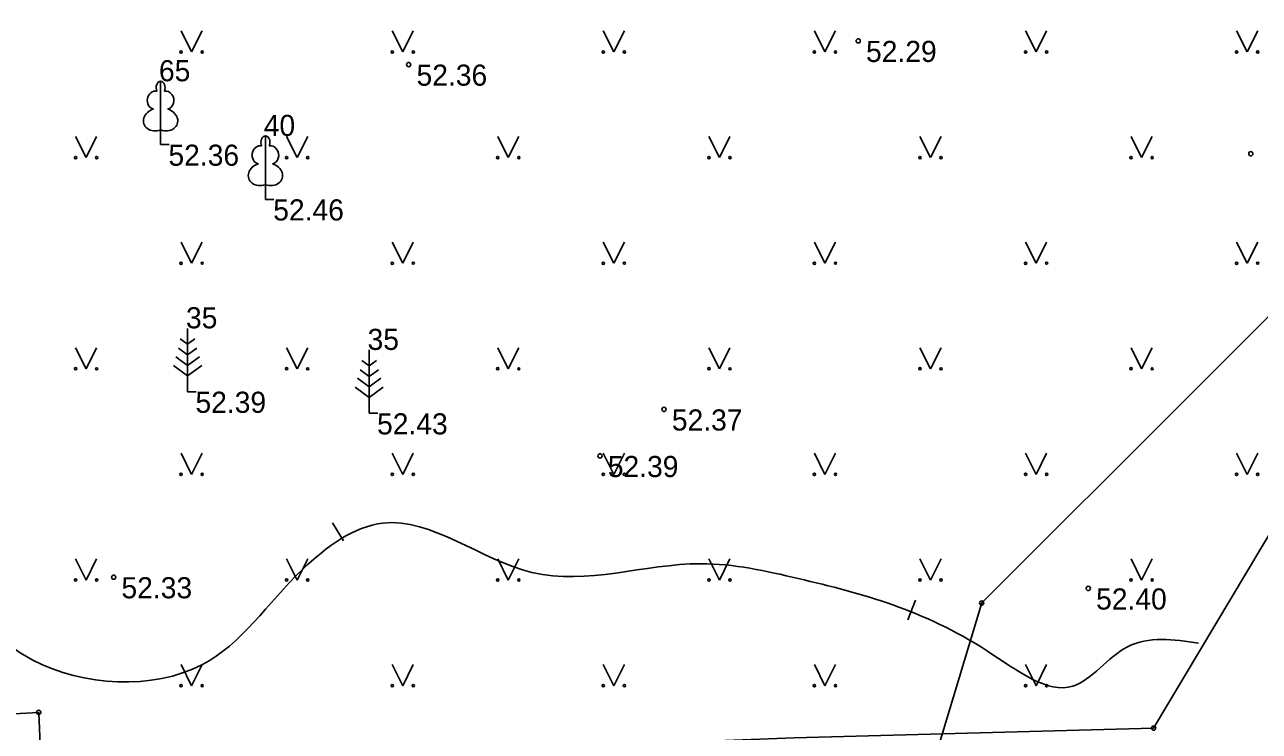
# Model space of a CAD drawing. Extents: x 619806 to 620082, y 405176 to 405386.
# Drawn here: x 619868.55 to 619897.79, y 405291.42 to 405308.14 of the extents above; entities that cross this region are included whole.
import ezdxf

# ---------------------------------------------------------------- set-up
doc = ezdxf.new("R2010")
doc.units = 0
for name, color, linetype in [('APGS_VADP_ZSPR_####_#', 7, 'Continuous'), ('CELI_CMAL_####_####_#', 7, 'Continuous'), ('RELJ_AATZ_####_TKST_#', 7, 'Continuous'), ('RELJ_ELEM_####_####_#', 7, 'Continuous'), ('RELJ_HORZ_PAMT_####_#', 7, 'Continuous'), ('TERT_DIAM_####_TKST_#', 7, 'Continuous'), ('TERT_ELEM_####_####_#', 7, 'Continuous')]:
    doc.layers.add(name, color=color, linetype=linetype)

msp = doc.modelspace()

# ---------------------------------------------------------------- linework, layer by layer
at = {"layer": 'APGS_VADP_ZSPR_####_#'}
msp.add_lwpolyline([(619926.053, 405342.093), (619924.906, 405341.871), (619913.437, 405323.942), (619914.167, 405323.421), (619913.311, 405323.727), (619901.199, 405304.503), (619901.88, 405304.137), (619901.118, 405304.337), (619891.212, 405294.458), (619889.151, 405287.633)], dxfattribs=at)
at = {"layer": 'CELI_CMAL_####_####_#'}
msp.add_lwpolyline([(619901.141, 405301.297), (619895.285, 405291.495), (619886.767, 405291.266), (619876.357, 405290.867), (619868.929, 405290.713), (619868.879, 405291.869), (619865.764, 405291.699), (619865.807, 405290.556), (619863.458, 405290.505), (619853.554, 405290.137), (619841.43, 405289.76), (619840.169, 405289.507), (619836.17, 405288.32), (619833.502, 405287.788), (619826.905, 405297.999), (619827.372, 405299.068), (619837.906, 405304.107), (619846.534, 405308.229), (619856.914, 405313.201), (619868.255, 405318.592), (619880.738, 405324.67), (619889.516, 405328.858), (619904.867, 405336.211)], dxfattribs=at)
at = {"layer": 'RELJ_ELEM_####_####_#'}
for centre in [(619888.287, 405307.762), (619877.641, 405307.201), (619897.586, 405305.09), (619883.688, 405299.039), (619882.171, 405297.938), (619870.652, 405295.068), (619893.736, 405294.802), (619891.212, 405294.458), (619868.879, 405291.869), (619895.285, 405291.495)]:
    msp.add_circle(centre, 0.05, dxfattribs=at)
at = {"layer": 'RELJ_HORZ_PAMT_####_#'}
for p, q in [((619875.834, 405296.356), (619876.098, 405295.931)), ((619889.647, 405294.525), (619889.465, 405294.06))]:
    msp.add_line(p, q, dxfattribs=at)
msp.add_spline([(619896.346, 405293.509), (619894.668, 405293.42), (619893.372, 405292.489), (619891.349, 405293.319), (619886.863, 405295.038), (619884.556, 405295.387), (619880.561, 405295.181), (619877.029, 405296.347), (619875.125, 405295.25), (619872.741, 405292.993), (619868.738, 405293.105), (619866.791, 405295.071), (619865.088, 405296.98), (619863.053, 405296.079), (619860.996, 405293.537), (619856.488, 405293.095), (619852.645, 405293.374), (619849.391, 405295.245), (619849.08, 405296.066), (619849.436, 405297.5), (619848.114, 405298.857), (619845.722, 405300.218), (619843.589, 405299.958), (619840.501, 405300.72), (619839.187, 405301.782), (619838.112, 405302.478), (619838.665, 405303.995), (619839.645, 405304.937)], degree=3, dxfattribs=at)
at = {"layer": 'TERT_ELEM_####_####_#'}
for p, q in [((619872.25, 405308), (619872.5, 405307.5)), ((619872.5, 405307.5), (619872.75, 405308)), ((619877.25, 405308), (619877.5, 405307.5)), ((619877.5, 405307.5), (619877.75, 405308)), ((619882.25, 405308), (619882.5, 405307.5)), ((619882.5, 405307.5), (619882.75, 405308)), ((619887.25, 405308), (619887.5, 405307.5)), ((619887.5, 405307.5), (619887.75, 405308)), ((619892.25, 405308), (619892.5, 405307.5)), ((619892.5, 405307.5), (619892.75, 405308)), ((619897.25, 405308), (619897.5, 405307.5)), ((619897.5, 405307.5), (619897.75, 405308)), ((619869.75, 405305.5), (619870, 405305)), ((619870, 405305), (619870.25, 405305.5)), ((619871.765, 405305.653), (619871.765, 405305.306)), ((619874.75, 405305.5), (619875, 405305)), ((619875, 405305), (619875.25, 405305.5)), ((619879.75, 405305.5), (619880, 405305)), ((619880, 405305), (619880.25, 405305.5)), ((619884.75, 405305.5), (619885, 405305)), ((619885, 405305), (619885.25, 405305.5)), ((619889.75, 405305.5), (619890, 405305)), ((619890, 405305), (619890.25, 405305.5)), ((619894.75, 405305.5), (619895, 405305)), ((619895, 405305), (619895.25, 405305.5)), ((619871.765, 405305.306), (619871.965, 405305.306)), ((619874.247, 405304.358), (619874.247, 405304.011)), ((619874.247, 405304.011), (619874.447, 405304.011)), ((619872.25, 405303), (619872.5, 405302.5)), ((619872.5, 405302.5), (619872.75, 405303)), ((619877.25, 405303), (619877.5, 405302.5)), ((619877.5, 405302.5), (619877.75, 405303)), ((619882.25, 405303), (619882.5, 405302.5)), ((619882.5, 405302.5), (619882.75, 405303)), ((619887.25, 405303), (619887.5, 405302.5)), ((619887.5, 405302.5), (619887.75, 405303)), ((619892.25, 405303), (619892.5, 405302.5)), ((619892.5, 405302.5), (619892.75, 405303)), ((619897.25, 405303), (619897.5, 405302.5)), ((619897.5, 405302.5), (619897.75, 405303)), ((619872.405, 405300.582), (619872.229, 405300.71)), ((619872.405, 405300.958), (619872.405, 405299.458)), ((619872.405, 405300.582), (619872.579, 405300.71)), ((619869.75, 405300.5), (619870, 405300)), ((619870, 405300), (619870.25, 405300.5)), ((619872.405, 405300.332), (619872.189, 405300.49)), ((619872.405, 405300.332), (619872.621, 405300.49)), ((619874.75, 405300.5), (619875, 405300)), ((619875, 405300), (619875.25, 405300.5)), ((619876.706, 405300.447), (619876.706, 405298.947)), ((619879.75, 405300.5), (619880, 405300)), ((619880, 405300), (619880.25, 405300.5)), ((619884.75, 405300.5), (619885, 405300)), ((619885, 405300), (619885.25, 405300.5)), ((619889.75, 405300.5), (619890, 405300)), ((619890, 405300), (619890.25, 405300.5)), ((619894.75, 405300.5), (619895, 405300)), ((619895, 405300), (619895.25, 405300.5)), ((619872.405, 405300.082), (619872.127, 405300.286)), ((619872.405, 405300.082), (619872.683, 405300.286)), ((619876.706, 405300.071), (619876.53, 405300.199)), ((619876.706, 405300.071), (619876.88, 405300.199)), ((619872.405, 405299.832), (619872.073, 405300.076)), ((619872.405, 405299.832), (619872.739, 405300.076)), ((619876.706, 405299.821), (619876.49, 405299.979)), ((619876.706, 405299.821), (619876.922, 405299.979)), ((619876.706, 405299.321), (619876.374, 405299.565)), ((619876.706, 405299.571), (619876.428, 405299.775)), ((619876.706, 405299.571), (619876.984, 405299.775)), ((619876.706, 405299.321), (619877.04, 405299.565)), ((619872.405, 405299.458), (619872.605, 405299.458)), ((619876.706, 405298.947), (619876.906, 405298.947)), ((619872.25, 405298), (619872.5, 405297.5)), ((619872.5, 405297.5), (619872.75, 405298)), ((619877.25, 405298), (619877.5, 405297.5)), ((619877.5, 405297.5), (619877.75, 405298)), ((619882.25, 405298), (619882.5, 405297.5)), ((619882.5, 405297.5), (619882.75, 405298)), ((619887.25, 405298), (619887.5, 405297.5)), ((619887.5, 405297.5), (619887.75, 405298)), ((619892.25, 405298), (619892.5, 405297.5)), ((619892.5, 405297.5), (619892.75, 405298)), ((619897.25, 405298), (619897.5, 405297.5)), ((619897.5, 405297.5), (619897.75, 405298)), ((619869.75, 405295.5), (619870, 405295)), ((619870, 405295), (619870.25, 405295.5)), ((619874.75, 405295.5), (619875, 405295)), ((619875, 405295), (619875.25, 405295.5)), ((619879.75, 405295.5), (619880, 405295)), ((619880, 405295), (619880.25, 405295.5)), ((619884.75, 405295.5), (619885, 405295)), ((619885, 405295), (619885.25, 405295.5)), ((619889.75, 405295.5), (619890, 405295)), ((619890, 405295), (619890.25, 405295.5)), ((619894.75, 405295.5), (619895, 405295)), ((619895, 405295), (619895.25, 405295.5)), ((619872.25, 405293), (619872.5, 405292.5)), ((619872.5, 405292.5), (619872.75, 405293)), ((619877.25, 405293), (619877.5, 405292.5)), ((619877.5, 405292.5), (619877.75, 405293)), ((619882.25, 405293), (619882.5, 405292.5)), ((619882.5, 405292.5), (619882.75, 405293)), ((619887.25, 405293), (619887.5, 405292.5)), ((619887.5, 405292.5), (619887.75, 405293)), ((619892.25, 405293), (619892.5, 405292.5)), ((619892.5, 405292.5), (619892.75, 405293))]:
    msp.add_line(p, q, dxfattribs=at)
for points in [[(619871.765, 405306.806), (619871.765, 405305.653)], [(619871.855, 405306.574), (619871.854, 405306.575)], [(619874.247, 405305.511), (619874.247, 405304.358)], [(619874.337, 405305.279), (619874.336, 405305.28)]]:
    msp.add_lwpolyline(points, dxfattribs=at)
for centre, radius in [((619872.25, 405307.5), 0.028), ((619872.75, 405307.5), 0.0263), ((619877.25, 405307.5), 0.028), ((619877.75, 405307.5), 0.0263), ((619882.25, 405307.5), 0.028), ((619882.75, 405307.5), 0.0263), ((619887.25, 405307.5), 0.028), ((619887.75, 405307.5), 0.0263), ((619892.25, 405307.5), 0.028), ((619892.75, 405307.5), 0.0263), ((619897.25, 405307.5), 0.028), ((619897.75, 405307.5), 0.0263), ((619869.75, 405305), 0.028), ((619870.25, 405305), 0.0263), ((619874.75, 405305), 0.028), ((619875.25, 405305), 0.0263), ((619879.75, 405305), 0.028), ((619880.25, 405305), 0.0263), ((619884.75, 405305), 0.028), ((619885.25, 405305), 0.0263), ((619889.75, 405305), 0.028), ((619890.25, 405305), 0.0263), ((619894.75, 405305), 0.028), ((619895.25, 405305), 0.0263), ((619872.25, 405302.5), 0.028), ((619872.75, 405302.5), 0.0263), ((619877.25, 405302.5), 0.028), ((619877.75, 405302.5), 0.0263), ((619882.25, 405302.5), 0.028), ((619882.75, 405302.5), 0.0263), ((619887.25, 405302.5), 0.028), ((619887.75, 405302.5), 0.0263), ((619892.25, 405302.5), 0.028), ((619892.75, 405302.5), 0.0263), ((619897.25, 405302.5), 0.028), ((619897.75, 405302.5), 0.0263), ((619869.75, 405300), 0.028), ((619870.25, 405300), 0.0263), ((619874.75, 405300), 0.028), ((619875.25, 405300), 0.0263), ((619879.75, 405300), 0.028), ((619880.25, 405300), 0.0263), ((619884.75, 405300), 0.028), ((619885.25, 405300), 0.0263), ((619889.75, 405300), 0.028), ((619890.25, 405300), 0.0263), ((619894.75, 405300), 0.028), ((619895.25, 405300), 0.0263), ((619872.25, 405297.5), 0.028), ((619872.75, 405297.5), 0.0263), ((619877.25, 405297.5), 0.028), ((619877.75, 405297.5), 0.0263), ((619882.25, 405297.5), 0.028), ((619882.75, 405297.5), 0.0263), ((619887.25, 405297.5), 0.028), ((619887.75, 405297.5), 0.0263), ((619892.25, 405297.5), 0.028), ((619892.75, 405297.5), 0.0263), ((619897.25, 405297.5), 0.028), ((619897.75, 405297.5), 0.0263), ((619869.75, 405295), 0.028), ((619870.25, 405295), 0.0263), ((619874.75, 405295), 0.028), ((619875.25, 405295), 0.0263), ((619879.75, 405295), 0.028), ((619880.25, 405295), 0.0263), ((619884.75, 405295), 0.028), ((619885.25, 405295), 0.0263), ((619889.75, 405295), 0.028), ((619890.25, 405295), 0.0263), ((619894.75, 405295), 0.028), ((619895.25, 405295), 0.0263), ((619872.25, 405292.5), 0.028), ((619872.75, 405292.5), 0.0263), ((619877.25, 405292.5), 0.028), ((619877.75, 405292.5), 0.0263), ((619882.25, 405292.5), 0.028), ((619882.75, 405292.5), 0.0263), ((619887.25, 405292.5), 0.028), ((619887.75, 405292.5), 0.0263), ((619892.25, 405292.5), 0.028), ((619892.75, 405292.5), 0.0263)]:
    msp.add_circle(centre, radius, dxfattribs=at)
for centre, major_axis, ratio, start_param, end_param in [((619871.637, 405306.361), (-0.039, -0.212), 0.861323, 3.141593, 6.283185), ((619871.765, 405306.656), (0, -0.15), 0.707107, 3.14537, 5.287485), ((619871.765, 405306.656), (0, -0.15), 0.707107, 0.995701, 3.137816), ((619871.893, 405306.361), (0.039, -0.212), 0.861323, 0, 3.141593), ((619871.675, 405305.899), (0.307, 0.095), 0.814445, 1.570796, 4.752015), ((619871.855, 405305.899), (-0.307, 0.095), 0.814445, 1.531171, 4.712389), ((619874.247, 405305.361), (0, -0.15), 0.707107, 3.14537, 5.287485), ((619874.247, 405305.361), (0, -0.15), 0.707107, 0.995701, 3.137816), ((619874.119, 405305.066), (-0.039, -0.212), 0.861323, 3.141593, 6.283185), ((619874.375, 405305.066), (0.039, -0.212), 0.861323, 0, 3.141593), ((619874.157, 405304.604), (0.307, 0.095), 0.814445, 1.570796, 4.752015), ((619874.337, 405304.604), (-0.307, 0.095), 0.814445, 1.531171, 4.712389)]:
    msp.add_ellipse(centre, major_axis=major_axis, ratio=ratio, start_param=start_param, end_param=end_param, dxfattribs=at)

# ---------------------------------------------------------------- texts
at = {"layer": 'RELJ_AATZ_####_TKST_#'}
for s, p in [(' 52.29', (619888.287, 405307.262)), (' 52.36', (619877.641, 405306.701)), (' 52.36', (619871.765, 405304.806)), (' 52.46', (619874.247, 405303.511)), (' 52.39', (619872.405, 405298.958)), (' 52.43', (619876.706, 405298.447)), (' 52.37', (619883.688, 405298.539)), (' 52.39', (619882.171, 405297.438)), (' 52.33', (619870.652, 405294.568)), (' 52.40', (619893.736, 405294.302))]:
    msp.add_text(s, height=0.5, dxfattribs=at).set_placement(p)
at = {"layer": 'TERT_DIAM_####_TKST_#'}
for s, p in [(' 65', (619871.54, 405306.806)), (' 40', (619874.022, 405305.511)), (' 35', (619872.18, 405300.958)), (' 35', (619876.481, 405300.447))]:
    msp.add_text(s, height=0.5, dxfattribs=at).set_placement(p)

doc.saveas('drawing.dxf')
